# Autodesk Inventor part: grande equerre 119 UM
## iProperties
Shininess: 21.0
Length Units: 11269
Angle Units: 11279
Time Units: 11290
Mass Units: 11283
Length Display Precision: 3
Angle Display Precision: 2
Created: 2001-03
Part Number: grande equerre 119 UM
Material: Par défaut
Document SubType Name: Tôlerie
Designer: jost
Density: 0.0
Volumn: 0.0
Area: 0.0
PropertySet Name: Model Information
Control State: 0
Master: False
Checked Out: False
Author: jost
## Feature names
1. Perçage1 [Hole]
2. Perçage2 [Hole]
3. Plaque1
4. Plaque2
5. Pli1
